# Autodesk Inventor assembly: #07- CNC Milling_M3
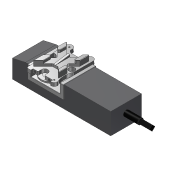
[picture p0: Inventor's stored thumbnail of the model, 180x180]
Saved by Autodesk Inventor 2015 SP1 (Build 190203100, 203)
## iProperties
Created: 2015-06
Part Number: #07- CNC Milling_M3
Document SubType Name: Assembly
Designer: suporte
Author: suporte
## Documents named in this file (3)
- C:\Users\suporte\Desktop\#07- CNC Milling\#07- CNC Milling_M3\#07- CNC Milling_M3.iam
- C:\Users\suporte\Desktop\#07- CNC Milling\#07- CNC Milling_M3\#07- CNC Milling_M3.ipt
- C:\Users\suporte\Desktop\#07- CNC Milling\#07- CNC Milling_M3\Small Clamp.ipt
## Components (2 placed, 2 different names)
1. #07- CNC Milling_M3:1 — Flush:1, Flush:2, Mate:1
2. Small Clamp:1 — Flush:1, Flush:2, Mate:1
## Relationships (3: Flush 2, Mate 1)
- Flush:1: #07- CNC Milling_M3:1 ↔ Small Clamp:1
- Flush:2: #07- CNC Milling_M3:1 ↔ Small Clamp:1
- Mate:1: #07- CNC Milling_M3:1 ↔ Small Clamp:1
